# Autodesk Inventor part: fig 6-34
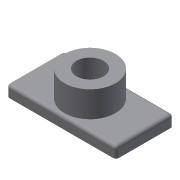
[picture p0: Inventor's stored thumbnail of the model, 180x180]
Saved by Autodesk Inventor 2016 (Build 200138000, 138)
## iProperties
Created: 2004-05
Part Number: fig 6-34
Document SubType Name: Modeling
Designer: CADCIM Technologies
Manufacturer: Standard
Standards Organization: Custom
Density: 1 g/cm^3
Material: Generic
Appearance: Default
Author: CADCIM Technologies
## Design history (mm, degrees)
sketch "Sketch1"
  geometry: L1 (-39.276, -18.692)-(33.721, -18.692); L2 (33.721, -18.692)-(33.721, 19.728); L3 (33.721, 19.728)-(-39.276, 19.728); L4 (-39.276, 19.728)-(-39.276, -18.692)
  constraints: 8 end point, 2 parallel, 1 horizontal, 1 perpendicular
extrude "Extrusion1" new body sketch "Sketch1" distance "d0" = 7.5; taper "d1" = 0 deg
sketch "Sketch2"
  geometry: C1 r 17 at (-2.778, 0.518)
  constraints: 1 centre point
  dimensions: "d16" = 34 diameter of C1
extrude "Extrusion2" join sketch "Sketch2" distance "d3" = 17.25; taper "d4" = 0 deg
hole "Hole1" diameter "d8" = 18; stored, may be unused: countersink angle "d12" = 90 deg, drill point angle "d14" = 118 deg; dims "d6" = 10, "d7" = 10, "d9" = 6, "d10" = 4, "d11" = 2, "d13" = 8
fillet "Fillet4" dims "d17" = 2
body "Solid1"
